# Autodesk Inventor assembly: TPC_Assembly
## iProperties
Shininess: 64.0
Length Units: 11269
Angle Units: 11279
Time Units: 11290
Mass Units: 11283
Length Display Precision: 3
Angle Display Precision: 2
Compacted: True
Created: 2004-08
Part Number: TPC_Assembly
Document SubType Name: Assembly
Designer: John Blackburn
Manufacturer: Standard
Standards Organization: Custom
Density: 0.0
Volumn: 0.0
Area: 0.0
PropertySet Name: Model Information
Control State: 0
Master: False
Checked Out: False
Author: John Blackburn
